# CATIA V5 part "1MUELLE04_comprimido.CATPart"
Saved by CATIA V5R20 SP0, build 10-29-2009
Part number: 1MUELLE04_comprimido
Revision: ANY
Definition: UNKNOWN
Nomenclature: 1MUELLE04_comprimido
Source: Unknown
Bounding box of the stored display mesh (mm): x -3.9 to 3.9, y -3.9 to 3.9, z -0.001 to 8.199
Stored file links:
  C:\Users\Utente\Desktop\IO LAVORO\3D X SITO CF\CUMSA\3D files AE\AE 041620\1MUELLE04_comprimido.CATPart
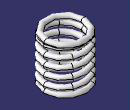
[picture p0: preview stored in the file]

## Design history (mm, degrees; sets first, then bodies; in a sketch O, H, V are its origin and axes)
Set1 "FacciaKO#NONE#14648"
  DatumSurface1 "Sup14648_1"
  DatumCurve1 "Crv14648_1"
Set2 "FacciaKO#NONE#4954"
  DatumSurface2 "Sup4954_1"
  DatumCurve2 "Crv4954_1"
Body1 "Cortar-Extruir1" (main body)
  Solid1: solid without history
